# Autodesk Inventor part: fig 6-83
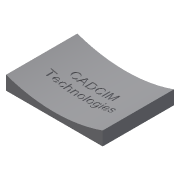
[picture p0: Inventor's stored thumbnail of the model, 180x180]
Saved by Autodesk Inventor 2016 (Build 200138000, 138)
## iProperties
Shininess: 64.0
Length Units: 11269
Angle Units: 11279
Time Units: 11290
Mass Units: 11283
Length Display Precision: 3
Angle Display Precision: 2
Compacted: True
Part Number: fig 6-83
Document SubType Name: Modeling
Created: 2002-12
Designer: deepak
Density: 1 g/cm^3
Material: Generic
Appearance: Default
Density: 0.0
Volumn: 0.0
Area: 0.0
PropertySet Name: Model Information
Control State: 0
Master: False
Checked Out: False
Author: deepak
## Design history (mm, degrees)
sketch "Sketch1"
  geometry: L1 (-39.922, 33.786)-(30.103, 33.786); L2 (30.103, 33.786)-(30.103, -17.894); L3 (30.103, -17.894)-(-39.922, -17.894); L4 (-39.922, -17.894)-(-39.922, 33.786)
  constraints: 8 end point, 2 parallel, 1 horizontal, 1 perpendicular
extrude "Extrusion1" new body sketch "Sketch1" distance "d0" = 10; taper "d1" = 0 deg
workplane "Work Plane1"
sketch "Sketch2"
  geometry: L1 (-37.656, 15.034)-(26.28, 15.034); L2 (26.28, 15.034)-(26.28, 10.168); L3 (26.28, 10.168)-(-37.656, 10.168); L4 (-37.656, 10.168)-(-37.656, 15.034)
  constraints: 2 other
sketch "Sketch3"
  geometry: L1 (70.026, 10)-(0, 10) reference; A1 r 105 centre (35.013, 108.99) between (0, 10) and (70.026, 10)
  constraints: 2 point on circle, 1 centre point
  dimensions: "d5" = 105 radius of A1
extrude "Extrusion2" cut sketch "Sketch3" stored distance "d3" = 10; taper "d4" = 0 deg
emboss "Emboss4" sketch "Sketch2" dims "d14" = 1, "d15" = 0
body "Solid1"
other parameters: "d2" = 5
